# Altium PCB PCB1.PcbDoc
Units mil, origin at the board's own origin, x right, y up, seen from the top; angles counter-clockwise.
Board outline 1355 x 1740 mil, 4 copper layers (Top Layer, GND, 3V3, Bottom Layer), stack 23.756 mil thick; 18 components, 15 nets, 70 pads, 4 vias.
Unrouted connection lines stored in the file: 37.
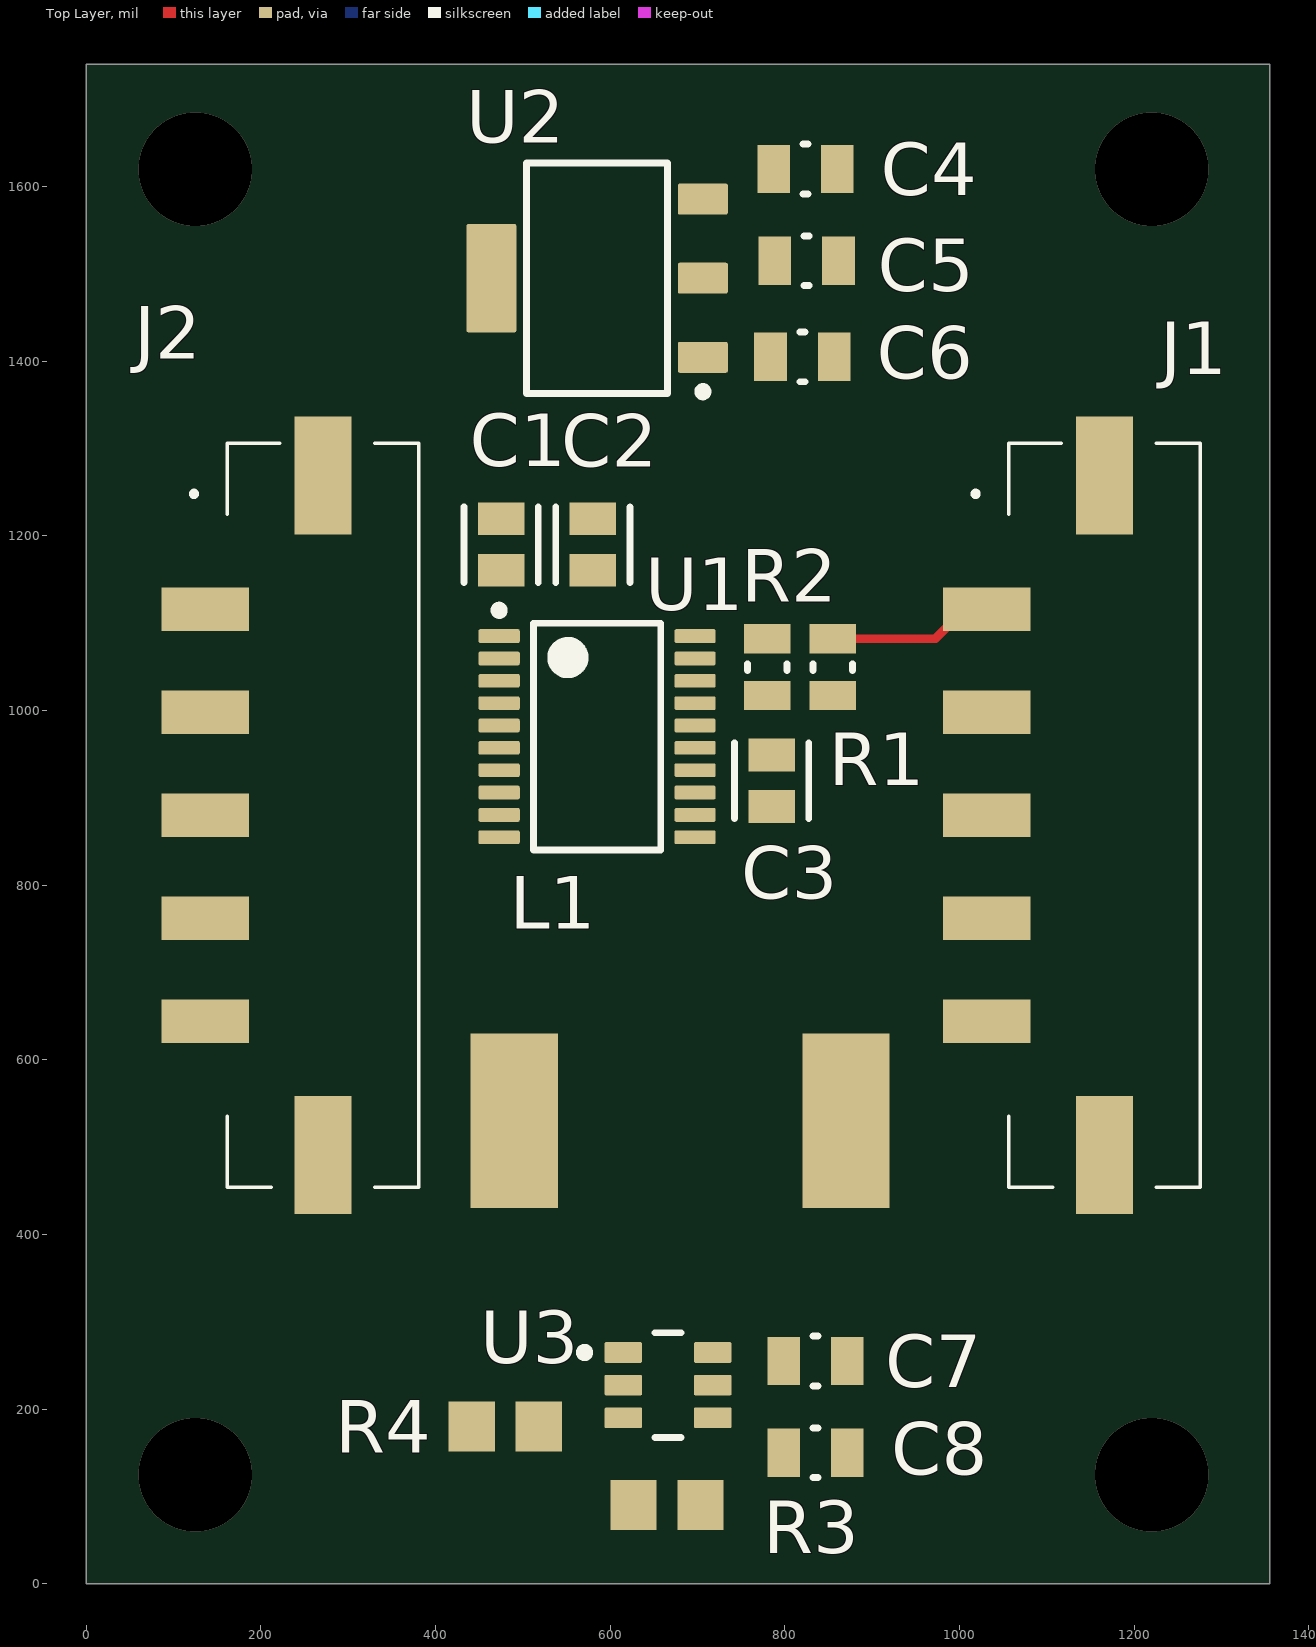
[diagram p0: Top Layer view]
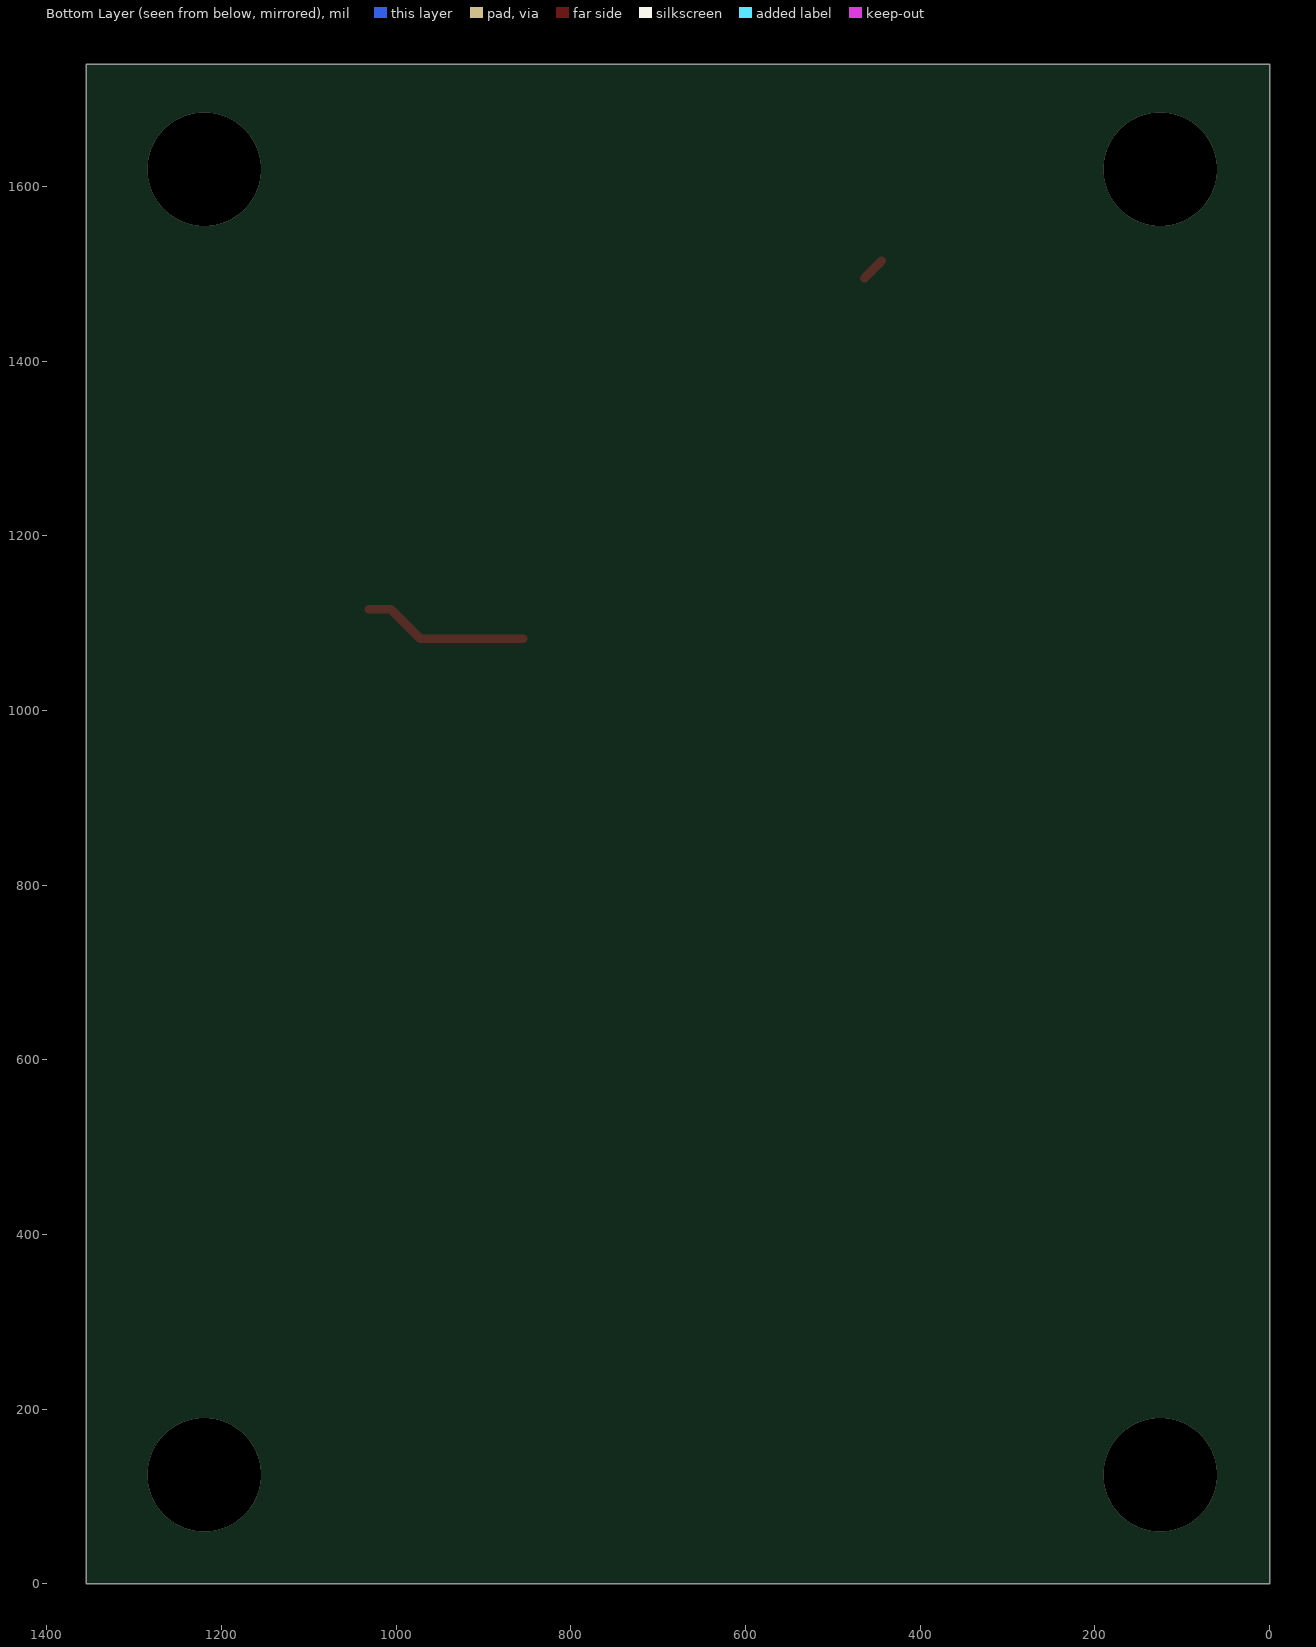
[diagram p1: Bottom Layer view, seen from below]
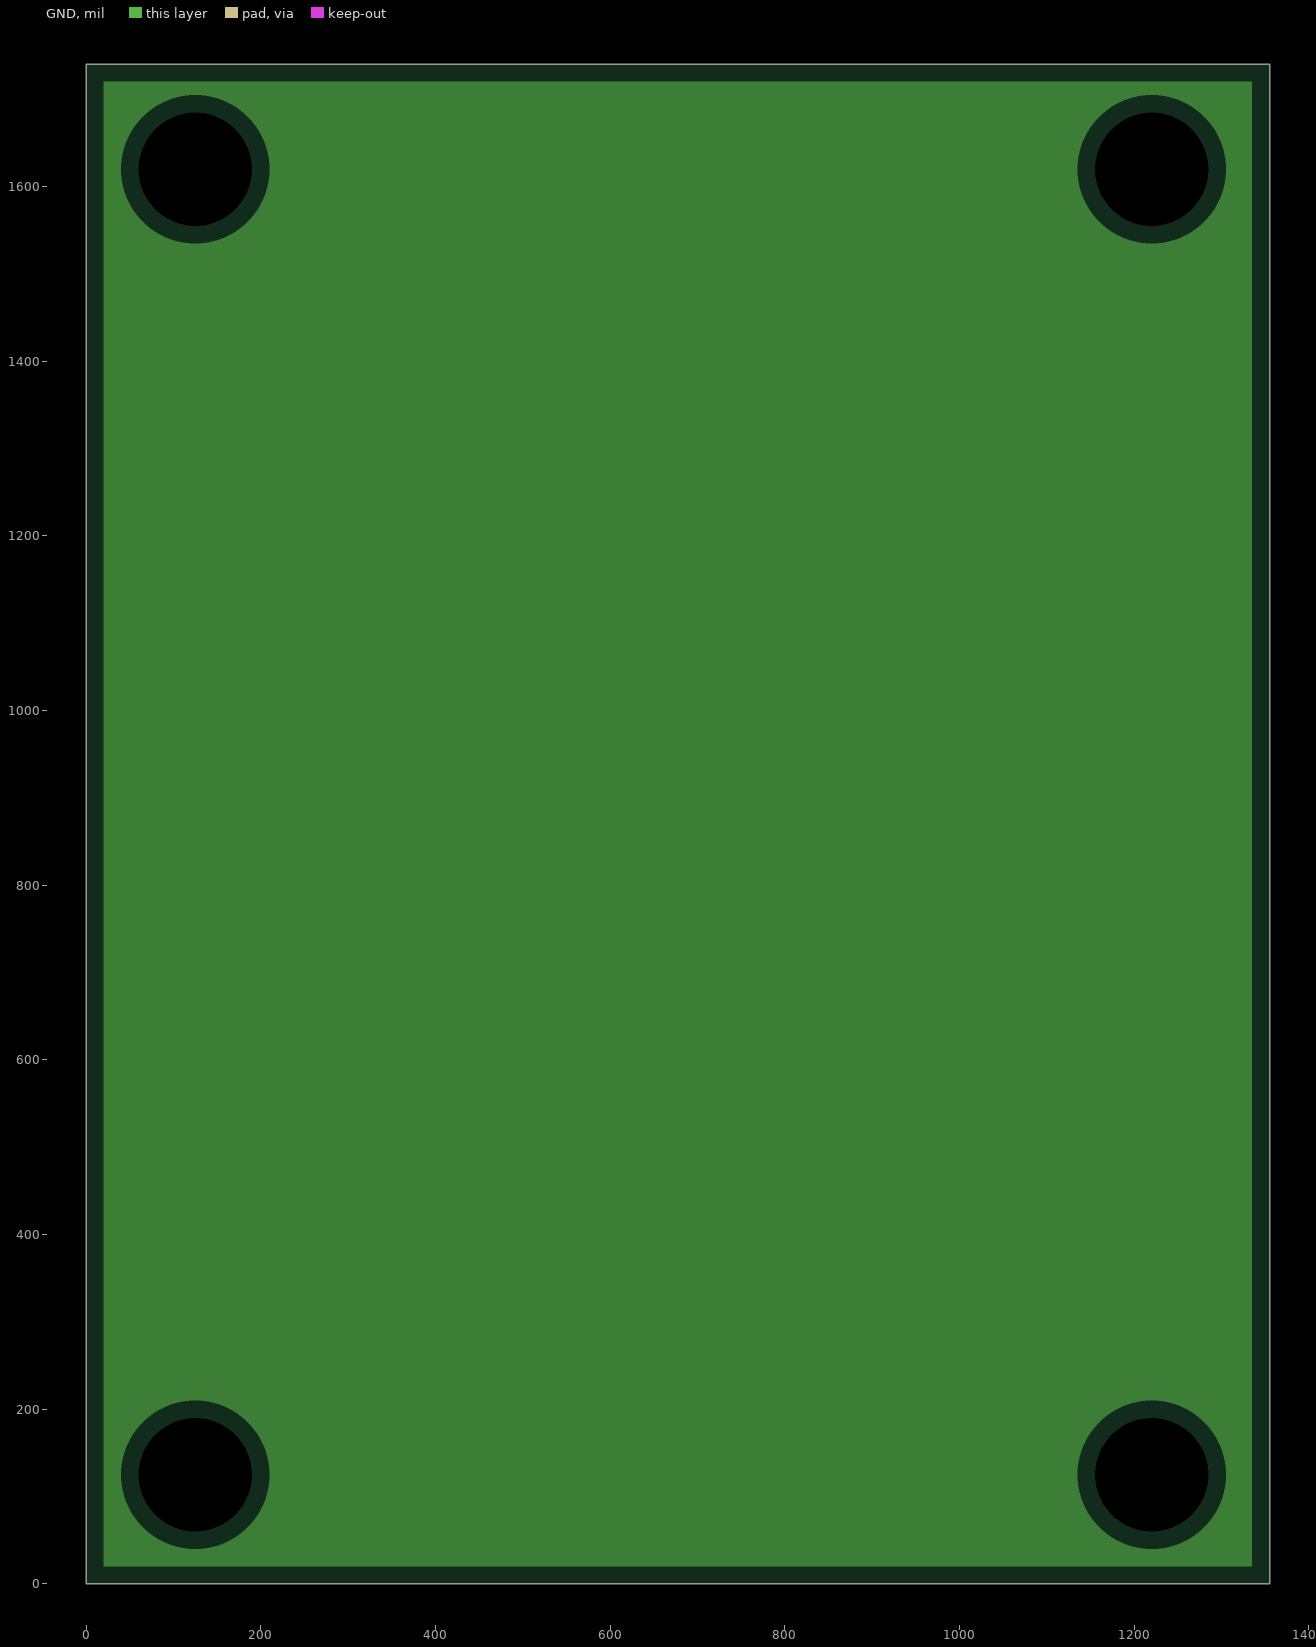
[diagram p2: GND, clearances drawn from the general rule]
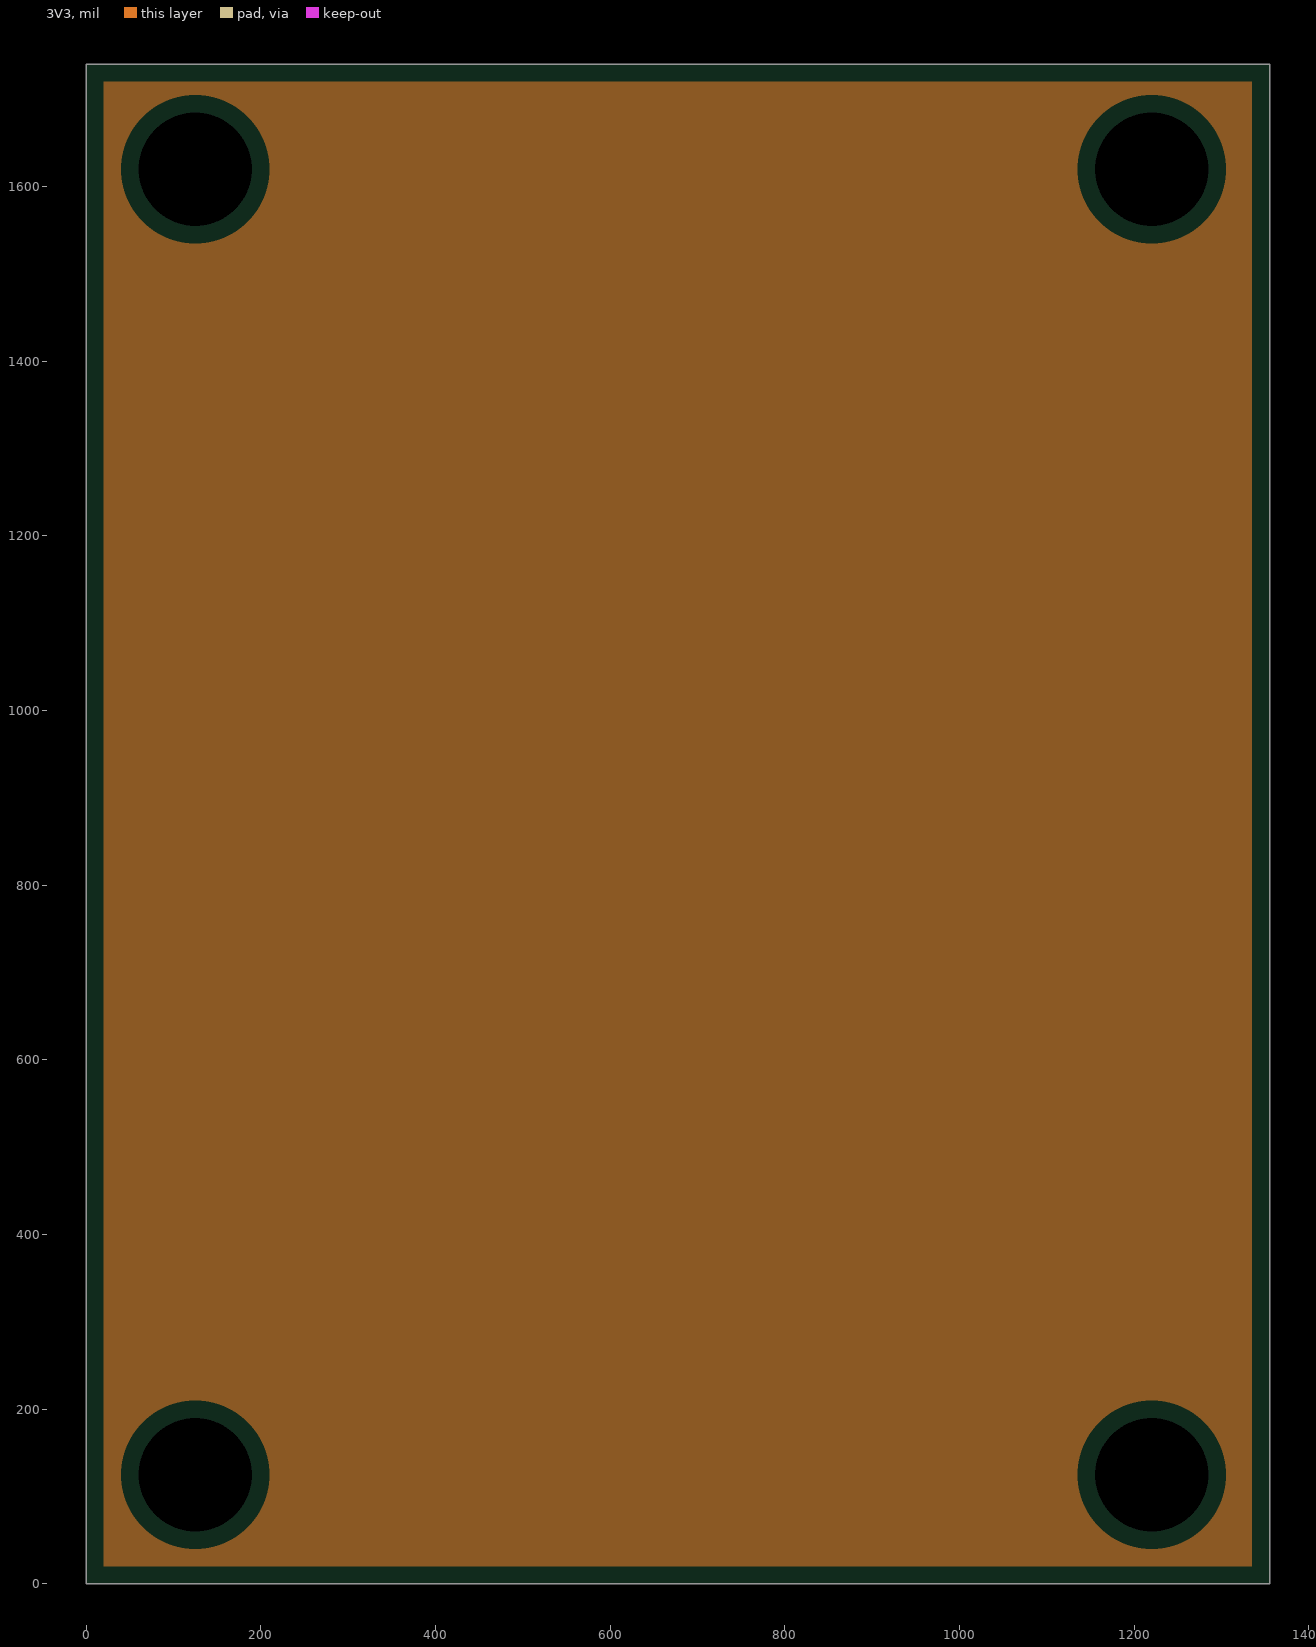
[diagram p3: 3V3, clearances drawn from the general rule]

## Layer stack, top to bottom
Top Solder: solder mask 0.4, Solder Resist, Dk 3.5
Top Layer: signal copper 1.4
Dielectric 2: prepreg 2.8, PP-006, Dk 4.1
GND: plane copper 1.378
Dielectric 1: dielectric 12.6, FR-4, Dk 4.8
3V3: plane copper 1.378
Dielectric 3: prepreg 2.8, PP-006, Dk 4.1
Bottom Layer: signal copper 1.4
Bottom Solder: solder mask 0.4, Solder Resist, Dk 3.5

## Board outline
0,0 1355,0 1355,1740 0,1740

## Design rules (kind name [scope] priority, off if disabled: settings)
Clearance [All] p1: gap=8 ignorepadtopadclearanceinfootprint=FALSE except(6: Arc-Arc Arc-Track Arc-SMDPad Arc-THPad Track-Track Track-SMDPad Track-THPad SMDPad-SMDPad SMDPad-THPad THPad-THPad Fill-Fill Fill-Poly Fill-Region Poly-Poly Poly-Region Region-Region; 10: Fill-Hole Poly-Hole Region-Hole)
PlaneClearance [All] p1: clearance=20
PlaneConnect [All] p1: planeconnectstyle=Relief reliefexpansion=20 reliefentries=4 reliefconductorwidth=10 reliefairgap=10
PolygonConnect [All] p1: connectstyle=Relief reliefconductorwidth=10 reliefentries=4 polygonreliefangle="90 Angle" airgapwidth=10
RoutingVias [All] p1: holewidth=28 width=50 viastyle="Through Hole" minholewidth=28 minwidth=50 maxholewidth=28 maxwidth=50
SolderMaskExpansion [All] p1: expansion=4 istentingtop=FALSE
Width [All] p1: maxlimit=10 minlimit=10 preferedwidth=10
28 further rules are at their usual default settings.

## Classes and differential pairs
component class "Power Supply": C4 C5 C6 C7 C8 L1 R3 R4 U2 U3
component class MCU: C1 C2 C3 J1 J2 R1 R2 U1

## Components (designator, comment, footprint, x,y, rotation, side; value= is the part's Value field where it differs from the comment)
C1 "10 uF" FP-C0805C-DG-MFG 475,1190 r90 top value=10uF
C2 "0.1 uF" FP-C0805C-DG-MFG 580,1190 r90 top value=10uF
C3 "1.1 nF" FP-C0805C-DG-MFG 785,919.53 r270 top value=10uF
C4 "4.7uF" FP-CC0805-0_85-MFG 823.58,1620 r0 top value="100 nF"
C5 "470nF" FP-CC0805-0_85-MFG 825,1515 r0 top value="100 nF"
C6 "4.7uF" FP-CC0805-0_85-MFG 820,1405 r0 top value="100 nF"
C7 "1uF" FP-CC0805-0_85-MFG 835,255 r0 top value="100 nF"
C8 "4.7uF" FP-CC0805-0_85-MFG 835,150 r180 top value="100 nF"
J1 "436500524" 436500524-Footprint-1 1165,880 r90 top
J2 "436500524" 436500524-Footprint-1 270,880 r90 top
L1 "Bourns SRU1048-100Y" "Bourns SRU1048-100Y-Footprint-1" 680,525 r0 top
R1 "47k" RESC2013X50X30LL20T20 855,1049.53 r90 top
R2 "1k" RESC2013X50X30LL20T20 780,1049.53 r90 top
R3 "Resistor 1k +/-1% 0805 125 mW" RESC2013X70X40ML20T20 665,90 r0 top value=1M
R4 "Resistor 1k +/-1% 0805 125 mW" RESC2013X70X40ML20T20 480,180 r0 top value=71.5k
U1 "MSP430G2553IPW20" PW0020A_L 585,970 r0 top
U2 "LM340MP-5.0/NOPB" DCY0004A_L 585,1495 r180 top
U3 "TLV61046ADBVT" FP-DBV0006A-MFG 666.18,227.4 r0 top

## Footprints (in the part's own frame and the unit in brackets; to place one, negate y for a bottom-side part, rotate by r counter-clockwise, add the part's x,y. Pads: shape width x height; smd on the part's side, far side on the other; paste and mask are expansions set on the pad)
436500524-Footprint-1 [mil]
  rect 50x100 smd: 1(236,133.65) 2(118,133.65) 3(0,133.65) 4(-118,133.65) 5(-236,133.65)
  rect 135.04x64.96 smd: MP1(-389.23,-1) MP2(389.23,-1)
  silkscreen extent -426,-111 426,149, body extent -446,-97 446,161, height 391
"Bourns SRU1048-100Y-Footprint-1" [mil]
  rect 100x200 smd: 1(190,5) 2(-190,5)
  body extent -197,-197 197,197, height 189
DCY0004A_L [mm] "SOT223, 4-Leads, Body 6.7x3.7mm, Pitch 2.3mm, IPC High Density"
  rrect11% 1.45x0.9 smd: 1(-3.075,2.3) 2(-3.075,0) 3(-3.075,-2.3)
  rrect7% 1.45x3.15 smd: 4(3.075,0)
  silkscreen extent -3.2,-3.35 2.05,3.42, body extent -3.5,-3.25 3.5,3.25, height 1.62
FP-C0805C-DG-MFG [mm]
  rect 0.95x1.35 smd paste+0 mask+0: 1(-0.75,0) 2(0.75,0)
  silkscreen extent -1.11,-1.08 1.1,1.07, body extent -1.4,-0.85 1.4,0.85, height 0.25
FP-CC0805-0_85-MFG [mm]
  rect 0.95x1.4 smd paste+0 mask+0: 1(-0.925,0) 2(0.925,0)
  silkscreen extent -0.08,-0.72 0.08,0.72, body extent -1.6,-1.05 1.6,1.05, height 0.25
FP-DBV0006A-MFG [mm]
  rrect17% 1.1x0.6 smd paste+0 mask+0: 1(-1.3,0.95) 2(-1.3,0) 3(-1.3,-0.95) 4(1.3,-0.95) 5(1.3,0) 6(1.3,0.95)
  silkscreen extent -2.55,-1.53 0.38,1.53, body extent -1.95,-1.78 1.95,1.78, height 0.25
PW0020A_L [mm] "SOP, 20-Leads, Body 6.6x4.5mm, Pitch 0.65mm, IPC High Density"
  rrect25% 1.2x0.4 smd: 1(-2.85,2.925) 2(-2.85,2.275) 3(-2.85,1.625) 4(-2.85,0.975) 5(-2.85,0.325) 6(-2.85,-0.325) 7(-2.85,-0.975) 8(-2.85,-1.625) 9(-2.85,-2.275) 10(-2.85,-2.925) 11(2.85,-2.925) 12(2.85,-2.275) 13(2.85,-1.625) 14(2.85,-0.975) 15(2.85,-0.325) 16(2.85,0.325) 17(2.85,0.975) 18(2.85,1.625) 19(2.85,2.275) 20(2.85,2.925)
  silkscreen extent -2.97,-3.3 1.85,3.8, body extent -3.21,-3.25 3.21,3.25, height 1
RESC2013X50X30LL20T20 [mm] "Chip Resistor, 2-Leads, Body 2.00x1.25mm, IPC High Density"
  rect 0.85x1.35 smd: 1(-0.825,0) 2(0.825,0)
  silkscreen extent -0.1,-0.58 0.1,0.58, body extent -1.1,-0.72 1.1,0.72, height 0.5
RESC2013X70X40ML20T20 [mm] "Chip Resistor, 2-Leads, Body 2.2x1.35mm, IPC Low Density"
  rect 1.35x1.45 smd: 1(-0.975,0) 2(0.975,0)
  body extent -1.1,-0.67 1.1,0.67, height 0.7

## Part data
C1 C2 C3: library part CMP-2007-03243-2, "CAP CER 10UF 10V X5R 0805", 3DS Part Number=220-00001, Capacitance=10uF, Manufacturer=Kemet, Manufacturer Part Number=C0805C106K8PACTU, Package=C0805C-DG, Temperature="-55°C to +85°C", Temperature Characteristic=X5R, Temperature Coefficient=15%, Temperature Range High=+85°C, Temperature Range Low=-55°C, Tolerance=10%, Voltage=10V
C4 C5 C6 C7 C8: library part CMP-03422-000499-1, "CAP CER 0.1UF 50V X7R 0805", Capacitance="100 nF", Manufacturer=Yageo, Manufacturer Part Number=CC0805KRX7R9BB104, Package=CC0805-0.85, Temperature="-30°C to +85°C", Temperature Characteristic=X7R, Temperature Range High=+85°C, Temperature Range Low=-30°C, Tolerance=0.1, Voltage Rating="50 V"
J1 J2: library part CMP-008-00009-1, "Micro-Fit 3.0 Vertical Header, 3.00mm Pitch, Single Row, 5 Circuits, with Solder Tab, Tin, Glow-Wire Capable, Black"
L1: library part CMP-006-00021-1, "Inductor"
R1 R2: library part CMP-2001-04896-1, Manufacturer="Vishay Dale", Part Number=CRCW08050000Z0EA
R3 R4: library part CMP-009-00010-4, "Chip Resistor, 1 KOhm, +/- 1%, 0.125 W, -55 to 155 degC, 0805 (2013 Metric)", Case/Package=0805, Max Operating Temperature=155°C, Min Operating Temperature=-55°C, Power=125mW, Tolerance=1%, Voltage Rating=150V
U1: library part CMP-0365-00585-2, "16 MHz Mixed Signal Microcontroller with 16 KB Flash, 512 B SRAM and 24 GPIOs, -40 to 85 degC, 20-pin SOP (PW), Green (RoHS & no Sb/Br)", Frequency(MHz)=16, Manufacturer="Texas Instruments", Temp Sensor=Yes
U2: library part CMP-0062-01784-3, "Series 3-Terminal Positive Regulators, 4-pin SOT-223, Pb-Free", Manufacturer="Texas Instruments", PackageTopMarking=XYTT*N00A, PowerWise=N
U3: library part CMP-04918-000055-1, "IC REG BOOST ADJ SOT23-6", Manufacturer="Texas Instruments", Max Junction Temp=+125°C, Max Supply Voltage=5.5V, Min Supply Voltage=1.8V, Nominal Supply Current=110uA, Output Current=980mA, Output Voltage=3.3-28V, Package=DBV0006A, Switching Frequency=1050kHz, Temperature="-40°C to +125°C", Temperature Range Low=-40°C

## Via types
v1: diameter 130, hole 130, Top Layer to Bottom Layer, 4 vias

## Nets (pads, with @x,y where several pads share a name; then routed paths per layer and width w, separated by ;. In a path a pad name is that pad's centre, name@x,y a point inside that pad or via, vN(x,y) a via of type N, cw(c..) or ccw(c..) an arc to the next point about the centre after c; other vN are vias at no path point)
+3.3V: C4.1 C5.1 U2.3
+3.7V: C6.1 U2.1
+3V3: C1.1 C2.1 J1.1 R1.2 U1.1 | length 190.4
  Top Layer w10: R1.2 972.36,1082.01 1006.35,1116 J1.1
+3V7: C7.1 L1.1 U3.6
+12V: C8.2 R3.2 U3.5
GND: C1.2 C2.2 C3.2 C4.2 C5.2 C6.2 C7.2 C8.1 J1.2 R2.2 R4.1 U1.20 U2.2 U2.4 U3.2 | length 28.3
  Top Layer w10: U2.4@443.94,1515 U2.4
"I2C SCL": J2.4 U1.9
"I2C SDA": J2.5 U1.10
NetL1_2: L1.2 U3.1
NetR3_1: R3.1 R4.2 U3.3
P1.0: J2.1 U1.2
P1.3: J2.2 U1.5
P1.4: J2.3 U1.6
TDIO: C3.1 J1.4 R1.1 U1.16
TEST: J1.3 R2.1 U1.17
pads on no net: J1.5 J1.MP1 J1.MP2 J2.MP1 J2.MP2 U1.3 U1.4 U1.7 U1.8 U1.11 U1.12 U1.13 U1.14 U1.15 U1.18 U1.19 U3.4
copper on no net:
  other v1: 125,125 1220,125 125,1620 1220,1620

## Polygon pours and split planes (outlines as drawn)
no net on GND (split plane): 1334.9,1719.9 1334.9,20.1 20.1,20.1 20.1,1719.9
no net on 3V3 (split plane): 1334.9,1719.9 1334.9,20.1 20.1,20.1 20.1,1719.9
